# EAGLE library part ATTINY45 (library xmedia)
MICROCONTROLLER 1K ROM 128 bytes RAM 128 bytes EEPROM
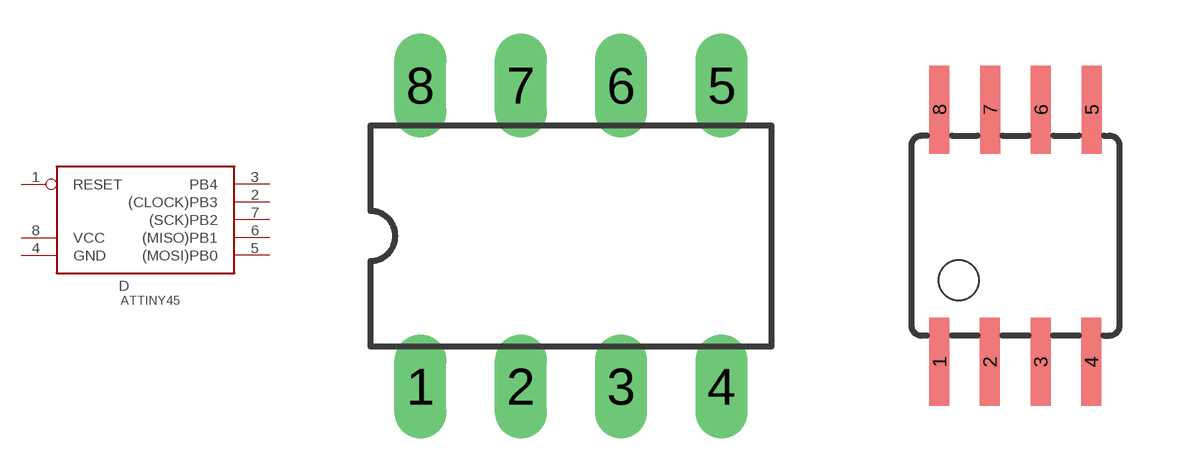
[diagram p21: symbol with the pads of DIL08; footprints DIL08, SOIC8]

Designator prefix D

## ATTINY45P  [DIL08]
1  RESET  in
2  (CLOCK)PB3
3  PB4
4  GND  pwr
5  (MOSI)PB0
6  (MISO)PB1
7  (SCK)PB2
8  VCC  pwr

## ATTINY45S  [SOIC8]
Pads as for DIL08

## Footprint DIL08 (pad centres in mm)
Dual In Line
drill 0.813 long: 1 -3.81,-3.81; 2 -1.27,-3.81; 3 1.27,-3.81; 4 3.81,-3.81; 5 3.81,3.81; 6 1.27,3.81; 7 -1.27,3.81; 8 -3.81,3.81

## Footprint SOIC8 (pad centres in mm)
Wide Plastic Gull Wing Small Outline Package
smd 0.5 x 2.2: 1 -1.905,-3.154; 2 -0.645,-3.154; 3 0.625,-3.154; 4 1.895,-3.154; 5 1.905,3.154; 6 0.635,3.154; 7 -0.635,3.154; 8 -1.905,3.154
